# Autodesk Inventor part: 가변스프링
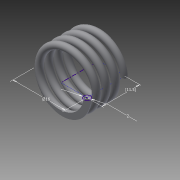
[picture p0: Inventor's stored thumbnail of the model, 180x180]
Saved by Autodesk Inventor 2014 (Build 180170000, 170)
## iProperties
Created: 2015-04
Part Number: 가변스프링
Material: Generic
Document SubType Name: Modeling
Designer: 시험용
Density: 1 g/cm^3
Appearance: Default
Mass: 0.608475 g
Surface Area: 12.5158 cm^2
Volume: 0.608475 cm^3
Author: 시험용
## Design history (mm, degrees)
sketch "스케치1"
  geometry: L1 (0, 0)-(8, 0); L2 (8, 0)-(8, 11.5); L3 (8, 11.5)-(0, 11.5); L4 (0, 11.5)-(0, 0); C1 r 1 at (8, 0)
  constraints: 8 end point, 2 parallel, 1 centre point, 1 coincident, 1 horizontal, 1 perpendicular
  dimensions: "d0" = 11.50049 distance of L1.end L2.end (derived); "d1" = 16 diameter of L2 L4; "d2" = 2 diameter of C1
feature "코일1" sketch "스케치1" pitch "d3" = 10; turns "d5" = 4; dims "d4" = 11.50049 (= d0), "d6" = 0, angle "d7" = 90 deg, angle "d8" = 90 deg, "d9" = 0, "d10" = 0
sketch "스케치2"
  geometry: L1 (-9, 0)-(-7, 0) reference; 1 further point
  constraints: 1 horizontal alignment
extrude "돌출1" cut sketch "스케치2" stored distance "d11" = 10; taper "d12" = 0 deg
node "작업 평면2"
sketch "스케치3"
  geometry: L1 (1, 0)-(-1, 0) reference; 1 further point
  constraints: 1 horizontal alignment
extrude "돌출2" cut sketch "스케치3" stored distance "d14" = 10; taper "d15" = 0 deg
node "솔리드1"
node "절단 모서리 투영1"
node "절단 모서리 투영2"
other parameters: "d13" = 0
